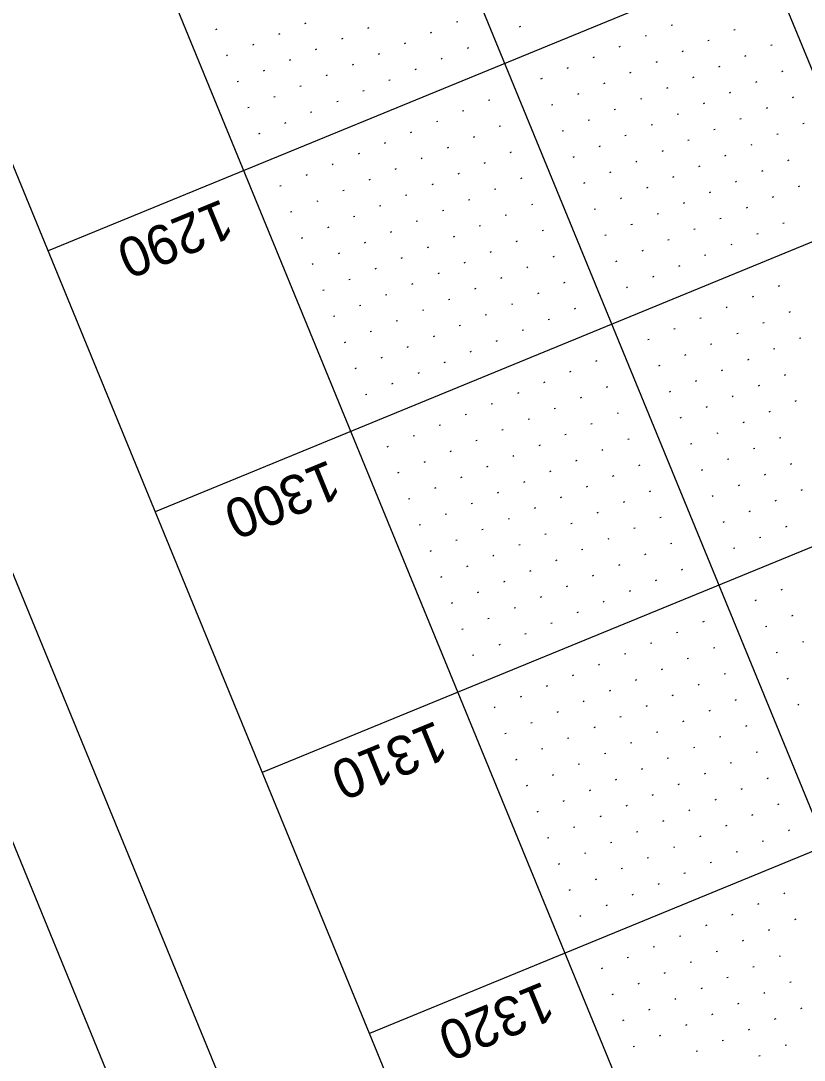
# Model space of a CAD drawing. Extents: x 2148770 to 2150891, y 142633 to 144465.
# Drawn here: x 2148940.4 to 2149079.4, y 143292.3 to 143476.6 of the extents above; entities that cross this region are included whole.
import ezdxf

# ---------------------------------------------------------------- set-up
doc = ezdxf.new("R2010")
doc.units = 0
for name, color, linetype in [('SHT_Plan_Profile_Sheet_Elev_Txt', 7, 'Continuous'), ('SHT_Plot_Shape_Full', 7, 'Continuous'), ('SHT_Plot_Shape_Half', 7, 'Continuous'), ('SHT_Profile_Grid_Major', 7, 'Continuous'), ('SHT_Profile_Grid_Minor', 7, 'Continuous'), ('SHT_Sheet_Border', 7, 'Continuous')]:
    doc.layers.add(name, color=color, linetype=linetype)

msp = doc.modelspace()

# ---------------------------------------------------------------- linework, layer by layer
at = {"layer": 'SHT_Plot_Shape_Full'}
msp.add_lwpolyline([(2150890.55, 143316.95), (2149225.42, 142633.31), (2148769.66, 143743.39), (2150434.78, 144427.04)], close=True, dxfattribs=at)
at = {"layer": 'SHT_Plot_Shape_Half'}
msp.add_lwpolyline([(2150799.14, 143324.02), (2149226.52, 142678.36), (2148808.74, 143695.93), (2150381.36, 144341.59)], close=True, dxfattribs=at)
at = {"layer": 'SHT_Profile_Grid_Major'}
for p, q in [((2150402.26, 144033.98), (2148945.27, 143435.79)), ((2150421.25, 143987.72), (2148964.26, 143389.54)), ((2150440.24, 143941.47), (2148983.25, 143343.29)), ((2150459.23, 143895.22), (2149002.24, 143297.03)), ((2149015.5, 143626.78), (2149167.42, 143256.75)), ((2148969.25, 143607.79), (2149121.17, 143237.76))]:
    msp.add_line(p, q, dxfattribs=at)
at = {"layer": 'SHT_Profile_Grid_Minor'}
for p, q in [((2149017.91, 143476.42), (2149017.68, 143476.33)), ((2148975.21, 143475.11), (2148974.98, 143475.01)), ((2148990.98, 143476.18), (2148990.75, 143476.08)), ((2149002.13, 143475.35), (2149001.9, 143475.26)), ((2149013.28, 143474.53), (2149013.05, 143474.43)), ((2149029.06, 143475.6), (2149028.83, 143475.5)), ((2149055.98, 143475.84), (2149055.75, 143475.75)), ((2149067.13, 143475.01), (2149066.9, 143474.92)), ((2148986.36, 143474.28), (2148986.13, 143474.19)), ((2148997.51, 143473.45), (2148997.28, 143473.36)), ((2149051.36, 143473.94), (2149051.13, 143473.85)), ((2149062.51, 143473.11), (2149062.28, 143473.02)), ((2148981.73, 143472.38), (2148981.5, 143472.29)), ((2148992.88, 143471.55), (2148992.65, 143471.46)), ((2149008.66, 143472.63), (2149008.43, 143472.53)), ((2149019.81, 143471.8), (2149019.58, 143471.7)), ((2149046.73, 143472.04), (2149046.5, 143471.95)), ((2149057.88, 143471.22), (2149057.65, 143471.12)), ((2149073.66, 143472.29), (2149073.43, 143472.19)), ((2148977.11, 143470.48), (2148976.88, 143470.39)), ((2148988.26, 143469.66), (2148988.03, 143469.56)), ((2149004.03, 143470.73), (2149003.8, 143470.63)), ((2149015.18, 143469.9), (2149014.95, 143469.8)), ((2149042.11, 143470.14), (2149041.88, 143470.05)), ((2149053.26, 143469.32), (2149053.03, 143469.22)), ((2149069.03, 143470.39), (2149068.8, 143470.29)), ((2148983.63, 143467.76), (2148983.4, 143467.66)), ((2148999.41, 143468.83), (2148999.18, 143468.73)), ((2149010.56, 143468), (2149010.33, 143467.91)), ((2149037.48, 143468.25), (2149037.25, 143468.15)), ((2149048.63, 143467.42), (2149048.4, 143467.32)), ((2149064.41, 143468.49), (2149064.17, 143468.39)), ((2149075.56, 143467.66), (2149075.32, 143467.57)), ((2148979.01, 143465.86), (2148978.78, 143465.76)), ((2148994.78, 143466.93), (2148994.55, 143466.83)), ((2149005.93, 143466.1), (2149005.7, 143466.01)), ((2149032.86, 143466.35), (2149032.62, 143466.25)), ((2149044.01, 143465.52), (2149043.77, 143465.42)), ((2149059.78, 143466.59), (2149059.55, 143466.5)), ((2149070.93, 143465.76), (2149070.7, 143465.67)), ((2148990.16, 143465.03), (2148989.92, 143464.94)), ((2149001.31, 143464.2), (2149001.07, 143464.11)), ((2149039.38, 143463.62), (2149039.15, 143463.52)), ((2149055.16, 143464.69), (2149054.92, 143464.6)), ((2149066.31, 143463.86), (2149066.07, 143463.77)), ((2148985.53, 143463.13), (2148985.3, 143463.04)), ((2148996.68, 143462.3), (2148996.45, 143462.21)), ((2149023.61, 143462.55), (2149023.37, 143462.45)), ((2149034.76, 143461.72), (2149034.52, 143461.63)), ((2149050.53, 143462.79), (2149050.3, 143462.7)), ((2149061.68, 143461.97), (2149061.45, 143461.87)), ((2149077.45, 143463.04), (2149077.22, 143462.94)), ((2148980.91, 143461.23), (2148980.67, 143461.14)), ((2148992.06, 143460.4), (2148991.82, 143460.31)), ((2149018.98, 143460.65), (2149018.75, 143460.55)), ((2149045.9, 143460.89), (2149045.67, 143460.8)), ((2149057.05, 143460.07), (2149056.82, 143459.97)), ((2149072.83, 143461.14), (2149072.6, 143461.04)), ((2148987.43, 143458.51), (2148987.2, 143458.41)), ((2149014.35, 143458.75), (2149014.12, 143458.66)), ((2149025.5, 143457.92), (2149025.27, 143457.83)), ((2149041.28, 143458.99), (2149041.05, 143458.9)), ((2149052.43, 143458.17), (2149052.2, 143458.07)), ((2149068.2, 143459.24), (2149067.97, 143459.14)), ((2149079.35, 143458.41), (2149079.12, 143458.32)), ((2148982.8, 143456.61), (2148982.57, 143456.51)), ((2149009.73, 143456.85), (2149009.5, 143456.76)), ((2149036.65, 143457.1), (2149036.42, 143457)), ((2149047.8, 143456.27), (2149047.57, 143456.17)), ((2149063.58, 143457.34), (2149063.35, 143457.24)), ((2149074.73, 143456.51), (2149074.5, 143456.42)), ((2149005.1, 143454.95), (2149004.87, 143454.86)), ((2149020.88, 143456.02), (2149020.65, 143455.93)), ((2149043.18, 143454.37), (2149042.95, 143454.27)), ((2149058.95, 143455.44), (2149058.72, 143455.35)), ((2149070.1, 143454.61), (2149069.87, 143454.52)), ((2149000.48, 143453.05), (2149000.25, 143452.96)), ((2149016.25, 143454.12), (2149016.02, 143454.03)), ((2149027.4, 143453.3), (2149027.17, 143453.2)), ((2149038.55, 143452.47), (2149038.32, 143452.38)), ((2149054.33, 143453.54), (2149054.1, 143453.45)), ((2149065.48, 143452.71), (2149065.25, 143452.62)), ((2148995.85, 143451.15), (2148995.62, 143451.06)), ((2149011.63, 143452.23), (2149011.4, 143452.13)), ((2149022.78, 143451.4), (2149022.55, 143451.3)), ((2149049.7, 143451.64), (2149049.47, 143451.55)), ((2149060.85, 143450.82), (2149060.62, 143450.72)), ((2149076.63, 143451.89), (2149076.4, 143451.79)), ((2148991.23, 143449.26), (2148991, 143449.16)), ((2149007, 143450.33), (2149006.77, 143450.23)), ((2149018.15, 143449.5), (2149017.92, 143449.4)), ((2149045.08, 143449.74), (2149044.85, 143449.65)), ((2149056.23, 143448.92), (2149056, 143448.82)), ((2149072, 143449.99), (2149071.77, 143449.89)), ((2148986.6, 143447.36), (2148986.37, 143447.26)), ((2149002.38, 143448.43), (2149002.15, 143448.33)), ((2149013.53, 143447.6), (2149013.3, 143447.51)), ((2149029.3, 143448.67), (2149029.07, 143448.58)), ((2149040.45, 143447.84), (2149040.22, 143447.75)), ((2149051.6, 143447.02), (2149051.37, 143446.92)), ((2149067.38, 143448.09), (2149067.15, 143447.99)), ((2149078.53, 143447.26), (2149078.3, 143447.17)), ((2148997.75, 143446.53), (2148997.52, 143446.43)), ((2149008.9, 143445.7), (2149008.67, 143445.61)), ((2149024.68, 143446.77), (2149024.45, 143446.68)), ((2149046.98, 143445.12), (2149046.75, 143445.02)), ((2149062.75, 143446.19), (2149062.52, 143446.1)), ((2149073.9, 143445.36), (2149073.67, 143445.27)), ((2148993.13, 143444.63), (2148992.9, 143444.53)), ((2149004.28, 143443.8), (2149004.05, 143443.71)), ((2149020.05, 143444.87), (2149019.82, 143444.78)), ((2149031.2, 143444.05), (2149030.97, 143443.95)), ((2149042.35, 143443.22), (2149042.12, 143443.12)), ((2149058.13, 143444.29), (2149057.89, 143444.2)), ((2149069.28, 143443.46), (2149069.04, 143443.37)), ((2148988.5, 143442.73), (2148988.27, 143442.64)), ((2148999.65, 143441.9), (2148999.42, 143441.81)), ((2149015.43, 143442.98), (2149015.2, 143442.88)), ((2149026.58, 143442.15), (2149026.34, 143442.05)), ((2149053.5, 143442.39), (2149053.27, 143442.3)), ((2149064.65, 143441.56), (2149064.42, 143441.47)), ((2148995.03, 143440), (2148994.79, 143439.91)), ((2149010.8, 143441.08), (2149010.57, 143440.98)), ((2149021.95, 143440.25), (2149021.72, 143440.15)), ((2149048.88, 143440.49), (2149048.64, 143440.4)), ((2149060.03, 143439.67), (2149059.79, 143439.57)), ((2149075.8, 143440.74), (2149075.57, 143440.64)), ((2148990.4, 143438.11), (2148990.17, 143438.01)), ((2149006.18, 143439.18), (2149005.94, 143439.08)), ((2149017.33, 143438.35), (2149017.09, 143438.25)), ((2149033.1, 143439.42), (2149032.87, 143439.33)), ((2149044.25, 143438.59), (2149044.02, 143438.5)), ((2149055.4, 143437.77), (2149055.17, 143437.67)), ((2149071.17, 143438.84), (2149070.94, 143438.74)), ((2149001.55, 143437.28), (2149001.32, 143437.18)), ((2149012.7, 143436.45), (2149012.47, 143436.36)), ((2149028.47, 143437.52), (2149028.24, 143437.43)), ((2149050.77, 143435.87), (2149050.54, 143435.77)), ((2149066.55, 143436.94), (2149066.32, 143436.84)), ((2148996.92, 143435.38), (2148996.69, 143435.28)), ((2149008.07, 143434.55), (2149007.84, 143434.46)), ((2149023.85, 143435.62), (2149023.62, 143435.53)), ((2149035, 143434.8), (2149034.77, 143434.7)), ((2149046.15, 143433.97), (2149045.92, 143433.87)), ((2149061.92, 143435.04), (2149061.69, 143434.95)), ((2148992.3, 143433.48), (2148992.07, 143433.39)), ((2149003.45, 143432.65), (2149003.22, 143432.56)), ((2149019.22, 143433.72), (2149018.99, 143433.63)), ((2149030.37, 143432.9), (2149030.14, 143432.8)), ((2149057.3, 143433.14), (2149057.07, 143433.05)), ((2148998.82, 143430.75), (2148998.59, 143430.66)), ((2149014.6, 143431.83), (2149014.37, 143431.73)), ((2149025.75, 143431), (2149025.52, 143430.9)), ((2149052.67, 143431.24), (2149052.44, 143431.15)), ((2148994.2, 143428.85), (2148993.97, 143428.76)), ((2149009.97, 143429.93), (2149009.74, 143429.83)), ((2149021.12, 143429.1), (2149020.89, 143429)), ((2149036.9, 143430.17), (2149036.67, 143430.08)), ((2149048.05, 143429.34), (2149047.82, 143429.25)), ((2149074.97, 143429.59), (2149074.74, 143429.49)), ((2149005.35, 143428.03), (2149005.12, 143427.93)), ((2149016.5, 143427.2), (2149016.27, 143427.11)), ((2149032.27, 143428.27), (2149032.04, 143428.18)), ((2149070.35, 143427.69), (2149070.12, 143427.59)), ((2149000.72, 143426.13), (2149000.49, 143426.03)), ((2149011.87, 143425.3), (2149011.64, 143425.21)), ((2149027.65, 143426.37), (2149027.42, 143426.28)), ((2149038.8, 143425.55), (2149038.57, 143425.45)), ((2149065.72, 143425.79), (2149065.49, 143425.69)), ((2149076.87, 143424.96), (2149076.64, 143424.87)), ((2148996.1, 143424.23), (2148995.87, 143424.13)), ((2149007.25, 143423.4), (2149007.02, 143423.31)), ((2149023.02, 143424.47), (2149022.79, 143424.38)), ((2149034.17, 143423.65), (2149033.94, 143423.55)), ((2149061.1, 143423.89), (2149060.87, 143423.8)), ((2149072.25, 143423.06), (2149072.02, 143422.97)), ((2149002.62, 143421.5), (2149002.39, 143421.41)), ((2149018.4, 143422.57), (2149018.17, 143422.48)), ((2149029.55, 143421.75), (2149029.32, 143421.65)), ((2149056.47, 143421.99), (2149056.24, 143421.9)), ((2149067.62, 143421.16), (2149067.39, 143421.07)), ((2148998, 143419.6), (2148997.77, 143419.51)), ((2149013.77, 143420.68), (2149013.54, 143420.58)), ((2149024.92, 143419.85), (2149024.69, 143419.75)), ((2149051.85, 143420.09), (2149051.61, 143420)), ((2149063, 143419.27), (2149062.76, 143419.17)), ((2149078.77, 143420.34), (2149078.54, 143420.24)), ((2149009.15, 143418.78), (2149008.91, 143418.68)), ((2149020.3, 143417.95), (2149020.06, 143417.85)), ((2149058.37, 143417.37), (2149058.14, 143417.27)), ((2149074.15, 143418.44), (2149073.91, 143418.34)), ((2149004.52, 143416.88), (2149004.29, 143416.78)), ((2149015.67, 143416.05), (2149015.44, 143415.96)), ((2149042.6, 143416.29), (2149042.36, 143416.2)), ((2149069.52, 143416.54), (2149069.29, 143416.44)), ((2148999.9, 143414.98), (2148999.66, 143414.88)), ((2149011.05, 143414.15), (2149010.81, 143414.06)), ((2149037.97, 143414.4), (2149037.74, 143414.3)), ((2149053.75, 143415.47), (2149053.51, 143415.37)), ((2149064.89, 143414.64), (2149064.66, 143414.55)), ((2149076.04, 143413.81), (2149075.81, 143413.72)), ((2149006.42, 143412.25), (2149006.19, 143412.16)), ((2149033.34, 143412.5), (2149033.11, 143412.4)), ((2149060.27, 143412.74), (2149060.04, 143412.65)), ((2149071.42, 143411.91), (2149071.19, 143411.82)), ((2149001.79, 143410.35), (2149001.56, 143410.26)), ((2149028.72, 143410.6), (2149028.49, 143410.5)), ((2149044.49, 143411.67), (2149044.26, 143411.57)), ((2149055.64, 143410.84), (2149055.41, 143410.75)), ((2149066.79, 143410.01), (2149066.56, 143409.92)), ((2149024.09, 143408.7), (2149023.86, 143408.6)), ((2149039.87, 143409.77), (2149039.64, 143409.68)), ((2149077.94, 143409.19), (2149077.71, 143409.09)), ((2149019.47, 143406.8), (2149019.24, 143406.7)), ((2149035.24, 143407.87), (2149035.01, 143407.78)), ((2149046.39, 143407.04), (2149046.16, 143406.95)), ((2149062.17, 143408.12), (2149061.94, 143408.02)), ((2149073.32, 143407.29), (2149073.09, 143407.19)), ((2149014.84, 143404.9), (2149014.61, 143404.81)), ((2149030.62, 143405.97), (2149030.39, 143405.88)), ((2149041.77, 143405.15), (2149041.54, 143405.05)), ((2149057.54, 143406.22), (2149057.31, 143406.12)), ((2149068.69, 143405.39), (2149068.46, 143405.29)), ((2149010.22, 143403), (2149009.99, 143402.91)), ((2149025.99, 143404.07), (2149025.76, 143403.98)), ((2149037.14, 143403.25), (2149036.91, 143403.15)), ((2149064.07, 143403.49), (2149063.84, 143403.4)), ((2149075.22, 143402.66), (2149074.99, 143402.57)), ((2149005.59, 143401.1), (2149005.36, 143401.01)), ((2149021.37, 143402.17), (2149021.14, 143402.08)), ((2149032.52, 143401.35), (2149032.29, 143401.25)), ((2149048.29, 143402.42), (2149048.06, 143402.32)), ((2149059.44, 143401.59), (2149059.21, 143401.5)), ((2149016.74, 143400.28), (2149016.51, 143400.18)), ((2149027.89, 143399.45), (2149027.66, 143399.35)), ((2149043.67, 143400.52), (2149043.44, 143400.42)), ((2149070.59, 143400.76), (2149070.36, 143400.67)), ((2149012.12, 143398.38), (2149011.89, 143398.28)), ((2149023.27, 143397.55), (2149023.04, 143397.45)), ((2149039.04, 143398.62), (2149038.81, 143398.53)), ((2149050.19, 143397.79), (2149049.96, 143397.7)), ((2149065.97, 143398.87), (2149065.74, 143398.77)), ((2149077.12, 143398.04), (2149076.88, 143397.94)), ((2149007.49, 143396.48), (2149007.26, 143396.38)), ((2149018.64, 143395.65), (2149018.41, 143395.56)), ((2149034.42, 143396.72), (2149034.19, 143396.63)), ((2149045.57, 143395.89), (2149045.33, 143395.8)), ((2149061.34, 143396.97), (2149061.11, 143396.87)), ((2149072.49, 143396.14), (2149072.26, 143396.04)), ((2149014.02, 143393.75), (2149013.78, 143393.66)), ((2149029.79, 143394.82), (2149029.56, 143394.73)), ((2149040.94, 143394), (2149040.71, 143393.9)), ((2149067.87, 143394.24), (2149067.63, 143394.14)), ((2149079.02, 143393.41), (2149078.78, 143393.32)), ((2149009.39, 143391.85), (2149009.16, 143391.76)), ((2149025.17, 143392.92), (2149024.93, 143392.83)), ((2149036.32, 143392.1), (2149036.08, 143392)), ((2149052.09, 143393.17), (2149051.86, 143393.07)), ((2149063.24, 143392.34), (2149063.01, 143392.25)), ((2149020.54, 143391.02), (2149020.31, 143390.93)), ((2149031.69, 143390.2), (2149031.46, 143390.1)), ((2149047.46, 143391.27), (2149047.23, 143391.17)), ((2149074.39, 143391.51), (2149074.16, 143391.42)), ((2149015.91, 143389.13), (2149015.68, 143389.03)), ((2149027.06, 143388.3), (2149026.83, 143388.2)), ((2149042.84, 143389.37), (2149042.61, 143389.28)), ((2149053.99, 143388.54), (2149053.76, 143388.45)), ((2149069.76, 143389.61), (2149069.53, 143389.52)), ((2149011.29, 143387.23), (2149011.06, 143387.13)), ((2149022.44, 143386.4), (2149022.21, 143386.3)), ((2149038.21, 143387.47), (2149037.98, 143387.38)), ((2149049.36, 143386.64), (2149049.13, 143386.55)), ((2149065.14, 143387.72), (2149064.91, 143387.62)), ((2149076.29, 143386.89), (2149076.06, 143386.79)), ((2149017.81, 143384.5), (2149017.58, 143384.41)), ((2149033.59, 143385.57), (2149033.36, 143385.48)), ((2149044.74, 143384.74), (2149044.51, 143384.65)), ((2149071.66, 143384.99), (2149071.43, 143384.89)), ((2149013.19, 143382.6), (2149012.96, 143382.51)), ((2149028.96, 143383.67), (2149028.73, 143383.58)), ((2149040.11, 143382.85), (2149039.88, 143382.75)), ((2149055.89, 143383.92), (2149055.66, 143383.82)), ((2149067.04, 143383.09), (2149066.81, 143383)), ((2149024.34, 143381.77), (2149024.11, 143381.68)), ((2149035.49, 143380.95), (2149035.26, 143380.85)), ((2149051.26, 143382.02), (2149051.03, 143381.92)), ((2149019.71, 143379.88), (2149019.48, 143379.78)), ((2149030.86, 143379.05), (2149030.63, 143378.95)), ((2149046.64, 143380.12), (2149046.41, 143380.02)), ((2149057.79, 143379.29), (2149057.56, 143379.2)), ((2149015.09, 143377.98), (2149014.86, 143377.88)), ((2149026.24, 143377.15), (2149026.01, 143377.05)), ((2149042.01, 143378.22), (2149041.78, 143378.13)), ((2149053.16, 143377.39), (2149052.93, 143377.3)), ((2149021.61, 143375.25), (2149021.38, 143375.15)), ((2149037.39, 143376.32), (2149037.16, 143376.23)), ((2149048.54, 143375.49), (2149048.31, 143375.4)), ((2149075.46, 143375.74), (2149075.23, 143375.64)), ((2149016.99, 143373.35), (2149016.76, 143373.26)), ((2149032.76, 143374.42), (2149032.53, 143374.33)), ((2149043.91, 143373.6), (2149043.68, 143373.5)), ((2149070.84, 143373.84), (2149070.6, 143373.74)), ((2149028.14, 143372.52), (2149027.91, 143372.43)), ((2149039.29, 143371.7), (2149039.05, 143371.6)), ((2149023.51, 143370.62), (2149023.28, 143370.53)), ((2149034.66, 143369.8), (2149034.43, 143369.7)), ((2149061.59, 143370.04), (2149061.35, 143369.95)), ((2149077.36, 143371.11), (2149077.13, 143371.02)), ((2149018.89, 143368.73), (2149018.65, 143368.63)), ((2149030.04, 143367.9), (2149029.8, 143367.8)), ((2149056.96, 143368.14), (2149056.73, 143368.05)), ((2149072.74, 143369.21), (2149072.5, 143369.12)), ((2149025.41, 143366), (2149025.18, 143365.9)), ((2149052.33, 143366.24), (2149052.1, 143366.15)), ((2149079.26, 143366.49), (2149079.03, 143366.39)), ((2149020.78, 143364.1), (2149020.55, 143364.01)), ((2149047.71, 143364.34), (2149047.48, 143364.25)), ((2149063.48, 143365.42), (2149063.25, 143365.32)), ((2149074.63, 143364.59), (2149074.4, 143364.49)), ((2149043.08, 143362.45), (2149042.85, 143362.35)), ((2149058.86, 143363.52), (2149058.63, 143363.42)), ((2149038.46, 143360.55), (2149038.23, 143360.45)), ((2149054.23, 143361.62), (2149054, 143361.52)), ((2149065.38, 143360.79), (2149065.15, 143360.7)), ((2149033.83, 143358.65), (2149033.6, 143358.55)), ((2149049.61, 143359.72), (2149049.38, 143359.62)), ((2149060.76, 143358.89), (2149060.53, 143358.8)), ((2149076.53, 143359.96), (2149076.3, 143359.87)), ((2149029.21, 143356.75), (2149028.98, 143356.65)), ((2149044.98, 143357.82), (2149044.75, 143357.73)), ((2149056.13, 143356.99), (2149055.9, 143356.9)), ((2149024.58, 143354.85), (2149024.35, 143354.75)), ((2149040.36, 143355.92), (2149040.13, 143355.83)), ((2149051.51, 143355.09), (2149051.28, 143355)), ((2149067.28, 143356.17), (2149067.05, 143356.07)), ((2149078.43, 143355.34), (2149078.2, 143355.24)), ((2149035.73, 143354.02), (2149035.5, 143353.93)), ((2149046.88, 143353.19), (2149046.65, 143353.1)), ((2149062.66, 143354.27), (2149062.43, 143354.17)), ((2149031.11, 143352.12), (2149030.88, 143352.03)), ((2149042.26, 143351.3), (2149042.03, 143351.2)), ((2149058.03, 143352.37), (2149057.8, 143352.27)), ((2149069.18, 143351.54), (2149068.95, 143351.45)), ((2149026.48, 143350.22), (2149026.25, 143350.13)), ((2149037.63, 143349.4), (2149037.4, 143349.3)), ((2149053.41, 143350.47), (2149053.18, 143350.37)), ((2149064.56, 143349.64), (2149064.32, 143349.55)), ((2149033.01, 143347.5), (2149032.77, 143347.4)), ((2149048.78, 143348.57), (2149048.55, 143348.47)), ((2149059.93, 143347.74), (2149059.7, 143347.65)), ((2149028.38, 143345.6), (2149028.15, 143345.5)), ((2149044.16, 143346.67), (2149043.92, 143346.58)), ((2149055.31, 143345.84), (2149055.07, 143345.75)), ((2149071.08, 143346.91), (2149070.85, 143346.82)), ((2149039.53, 143344.77), (2149039.3, 143344.68)), ((2149050.68, 143343.94), (2149050.45, 143343.85)), ((2149066.45, 143345.02), (2149066.22, 143344.92)), ((2149034.9, 143342.87), (2149034.67, 143342.78)), ((2149046.05, 143342.04), (2149045.82, 143341.95)), ((2149061.83, 143343.12), (2149061.6, 143343.02)), ((2149072.98, 143342.29), (2149072.75, 143342.19)), ((2149030.28, 143340.97), (2149030.05, 143340.88)), ((2149041.43, 143340.15), (2149041.2, 143340.05)), ((2149057.2, 143341.22), (2149056.97, 143341.12)), ((2149068.35, 143340.39), (2149068.12, 143340.3)), ((2149036.8, 143338.25), (2149036.57, 143338.15)), ((2149052.58, 143339.32), (2149052.35, 143339.22)), ((2149063.73, 143338.49), (2149063.5, 143338.4)), ((2149032.18, 143336.35), (2149031.95, 143336.25)), ((2149047.95, 143337.42), (2149047.72, 143337.32)), ((2149059.1, 143336.59), (2149058.87, 143336.5)), ((2149074.88, 143337.66), (2149074.65, 143337.57)), ((2149043.33, 143335.52), (2149043.1, 143335.43)), ((2149054.48, 143334.69), (2149054.25, 143334.6)), ((2149070.25, 143335.76), (2149070.02, 143335.67)), ((2149038.7, 143333.62), (2149038.47, 143333.53)), ((2149049.85, 143332.79), (2149049.62, 143332.7)), ((2149065.63, 143333.87), (2149065.4, 143333.77)), ((2149076.78, 143333.04), (2149076.55, 143332.94)), ((2149034.08, 143331.72), (2149033.85, 143331.63)), ((2149045.23, 143330.9), (2149045, 143330.8)), ((2149061, 143331.97), (2149060.77, 143331.87)), ((2149072.15, 143331.14), (2149071.92, 143331.04)), ((2149040.6, 143329), (2149040.37, 143328.9)), ((2149056.38, 143330.07), (2149056.15, 143329.97)), ((2149067.53, 143329.24), (2149067.3, 143329.15)), ((2149035.98, 143327.1), (2149035.75, 143327)), ((2149051.75, 143328.17), (2149051.52, 143328.07)), ((2149062.9, 143327.34), (2149062.67, 143327.25)), ((2149047.13, 143326.27), (2149046.9, 143326.18)), ((2149058.28, 143325.44), (2149058.04, 143325.35)), ((2149042.5, 143324.37), (2149042.27, 143324.28)), ((2149053.65, 143323.54), (2149053.42, 143323.45)), ((2149037.88, 143322.47), (2149037.64, 143322.38)), ((2149049.03, 143321.64), (2149048.79, 143321.55)), ((2149075.95, 143321.89), (2149075.72, 143321.79)), ((2149044.4, 143319.75), (2149044.17, 143319.65)), ((2149071.32, 143319.99), (2149071.09, 143319.89)), ((2149039.77, 143317.85), (2149039.54, 143317.75)), ((2149066.7, 143318.09), (2149066.47, 143318)), ((2149062.07, 143316.19), (2149061.84, 143316.1)), ((2149077.85, 143317.26), (2149077.62, 143317.17)), ((2149057.45, 143314.29), (2149057.22, 143314.2)), ((2149073.22, 143315.36), (2149072.99, 143315.27)), ((2149052.82, 143312.39), (2149052.59, 143312.3)), ((2149068.6, 143313.47), (2149068.37, 143313.37)), ((2149048.2, 143310.49), (2149047.97, 143310.4)), ((2149063.97, 143311.57), (2149063.74, 143311.47)), ((2149075.12, 143310.74), (2149074.89, 143310.64)), ((2149059.35, 143309.67), (2149059.12, 143309.57)), ((2149070.5, 143308.84), (2149070.27, 143308.75)), ((2149043.57, 143308.6), (2149043.34, 143308.5)), ((2149054.72, 143307.77), (2149054.49, 143307.67)), ((2149065.87, 143306.94), (2149065.64, 143306.85)), ((2149050.1, 143305.87), (2149049.87, 143305.77)), ((2149061.25, 143305.04), (2149061.02, 143304.95)), ((2149077.02, 143306.11), (2149076.79, 143306.02)), ((2149045.47, 143303.97), (2149045.24, 143303.88)), ((2149056.62, 143303.14), (2149056.39, 143303.05)), ((2149072.4, 143304.21), (2149072.17, 143304.12)), ((2149052, 143301.24), (2149051.76, 143301.15)), ((2149067.77, 143302.32), (2149067.54, 143302.22)), ((2149078.92, 143301.49), (2149078.69, 143301.39)), ((2149063.15, 143300.42), (2149062.91, 143300.32)), ((2149074.3, 143299.59), (2149074.06, 143299.49)), ((2149047.37, 143299.35), (2149047.14, 143299.25)), ((2149058.52, 143298.52), (2149058.29, 143298.42)), ((2149069.67, 143297.69), (2149069.44, 143297.6)), ((2149053.89, 143296.62), (2149053.66, 143296.52)), ((2149065.04, 143295.79), (2149064.81, 143295.7)), ((2149049.27, 143294.72), (2149049.04, 143294.62)), ((2149060.42, 143293.89), (2149060.19, 143293.8)), ((2149076.19, 143294.96), (2149075.96, 143294.87)), ((2149071.57, 143293.07), (2149071.34, 143292.97))]:
    msp.add_line(p, q, dxfattribs=at)
at = {"layer": 'SHT_Sheet_Border'}
msp.add_line((2148894.51, 143658.18), (2149074.91, 143218.77), dxfattribs=at)
msp.add_lwpolyline([(2150699.45, 143310.11), (2149242.47, 142711.93), (2148843.68, 143683.25), (2150300.66, 144281.43)], close=True, dxfattribs=at)

# ---------------------------------------------------------------- texts
at = {"layer": 'SHT_Plan_Profile_Sheet_Elev_Txt'}
for s, p in [('1290', (2148976.17, 143445.07)), ('1300', (2148995.16, 143398.81)), ('1310', (2149014.15, 143352.56)), ('1320', (2149033.14, 143306.31))]:
    msp.add_text(s, height=7, rotation=202.3213, dxfattribs=at).set_placement(p)

doc.saveas('drawing.dxf')
